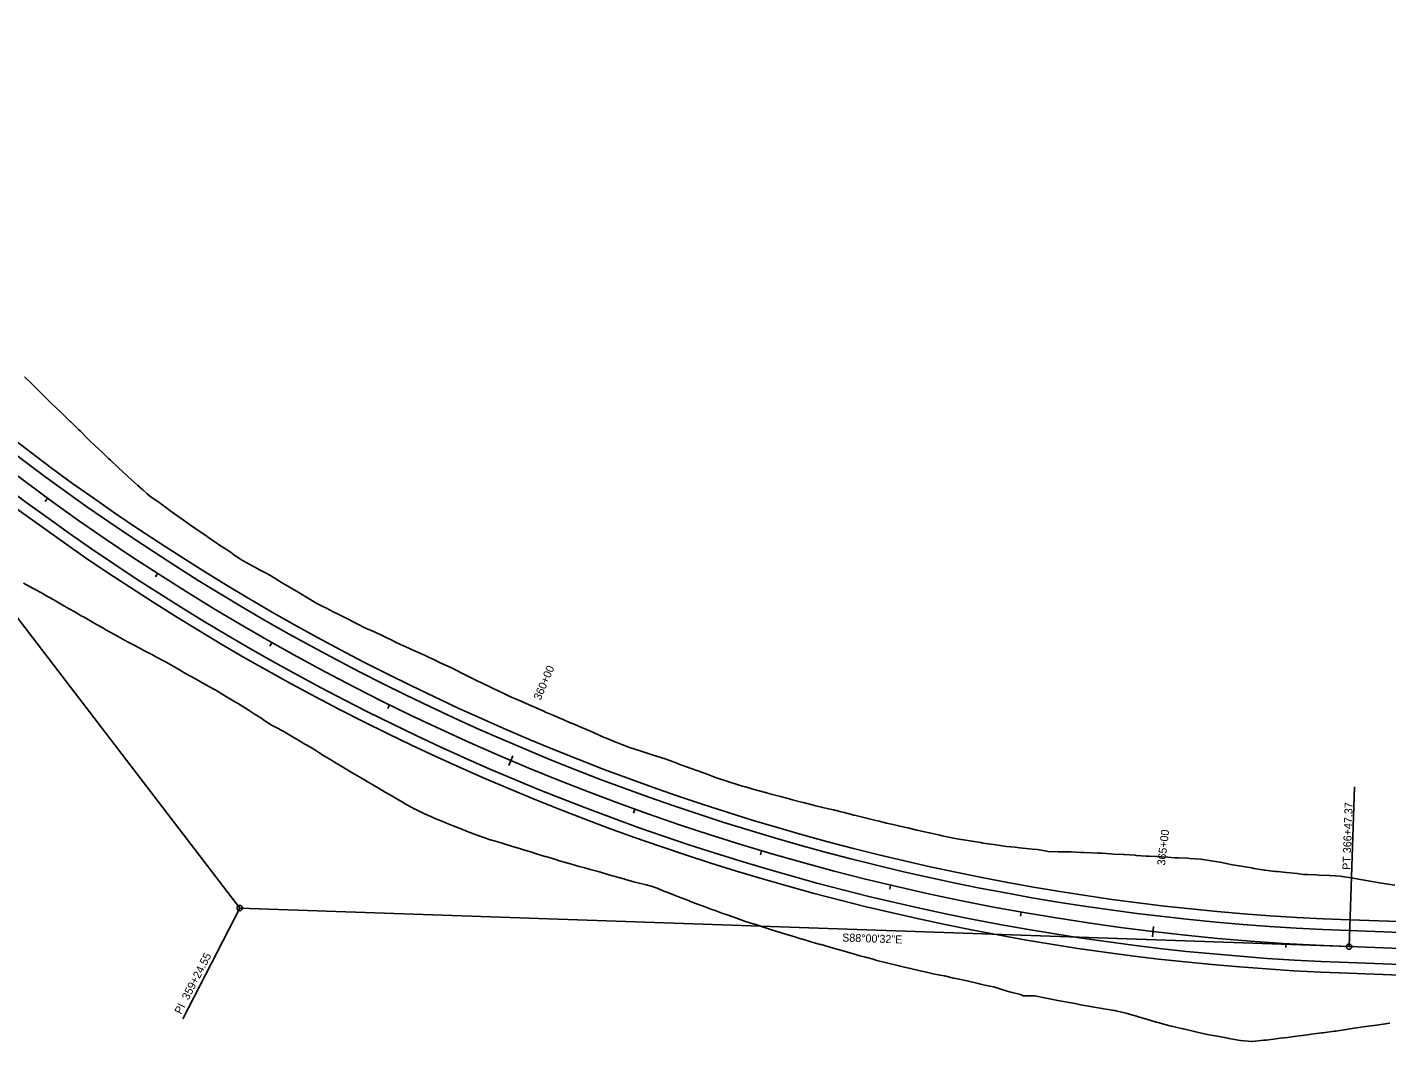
# Model space of a CAD drawing. Extents: x 881426 to 887360, y 1564404 to 1567430.
# Drawn here: x 884680 to 885699, y 1564437 to 1565198 of the extents above; entities that cross this region are included whole.
import ezdxf

# ---------------------------------------------------------------- set-up
doc = ezdxf.new("R2010")
doc.units = 0
for name, color, linetype in [('R_Horz Alg', 7, 'Continuous'), ('R_Horz Alg Annot', 7, 'Continuous'), ('R_Proposed Const Limits_Cut', 7, 'Continuous'), ('R_Proposed Const Limits_Fill', 7, 'Continuous'), ('R_Proposed Road_Lane', 7, 'Continuous'), ('R_Proposed Road_Shoulder', 7, 'Continuous')]:
    doc.layers.add(name, color=color, linetype=linetype)

msp = doc.modelspace()

# ---------------------------------------------------------------- linework, layer by layer
at = {"layer": 'R_Horz Alg'}
msp.add_line((885670.6, 1564508.7), (887357.7, 1564450), dxfattribs=at)
msp.add_arc((885731.8, 1566270.6), 1762.9, 217.4722, 268.0089, dxfattribs=at)
at = {"layer": 'R_Horz Alg Annot'}
for p, q in [((884332.7, 1565198), (884838.9, 1564537.6)), ((884838.9, 1564537.6), (885670.6, 1564508.7))]:
    msp.add_line(p, q, dxfattribs=at)
for points in [[(884693.1, 1564842.4), (884694.8, 1564844.9)], [(884775.7, 1564785.9), (884777.3, 1564788.4)], [(884861.4, 1564734), (884862.9, 1564736.6)], [(884949.9, 1564687.2), (884951.2, 1564689.9)], [(885043.7, 1564651.8), (885040.6, 1564644.5)], [(885670.6, 1564508.7), (885674.7, 1564628.6)], [(885134.2, 1564608.8), (885135.2, 1564611.6)], [(885229.4, 1564577.6), (885230.2, 1564580.5)], [(885326.2, 1564551.9), (885326.8, 1564554.8)], [(884838.9, 1564537.6), (884796.1, 1564454.5)], [(885424.2, 1564531.6), (885424.8, 1564534.6)], [(885524.1, 1564523.9), (885523.2, 1564516)], [(885623.1, 1564508), (885623.3, 1564511)]]:
    msp.add_lwpolyline(points, dxfattribs=at)
for centre in [(884838.9, 1564537.6), (885670.6, 1564508.7)]:
    msp.add_circle(centre, 2, dxfattribs=at)
at = {"layer": 'R_Proposed Const Limits_Cut'}
for points in [[(884841.5, 1564797.9), (884847, 1564794.9), (884850.1, 1564793.3), (884854.2, 1564791), (884858.7, 1564788.6), (884861.4, 1564787.1), (884867.1, 1564783.7), (884868.5, 1564782.8), (884875.4, 1564778.6), (884875.5, 1564778.6), (884882.6, 1564774.5), (884883.9, 1564773.7), (884889.6, 1564770.3), (884892.2, 1564768.6), (884896.6, 1564766)], [(885127.3, 1564659.4), (885131.2, 1564658.1), (885135.1, 1564656.8), (885140.5, 1564655.1), (885142.9, 1564654.3), (885149.7, 1564652.1), (885150.7, 1564651.7), (885158.5, 1564649.3), (885159, 1564649.1), (885166.2, 1564646.4), (885168.2, 1564645.6), (885173.9, 1564643.5), (885177.3, 1564642.2), (885181.6, 1564640.7), (885186.5, 1564638.9), (885189.3, 1564637.9), (885195.7, 1564635.6), (885197, 1564635.1), (885204.8, 1564632.4), (885204.9, 1564632.4)]]:
    msp.add_lwpolyline(points, dxfattribs=at)
at = {"layer": 'R_Proposed Const Limits_Fill'}
for points in [[(884677.6, 1564936), (884683, 1564930.6), (884684.5, 1564929.1), (884688.8, 1564924.8), (884691.4, 1564922.2), (884694.6, 1564919.1), (884698.3, 1564915.4), (884700.5, 1564913.3), (884705.4, 1564908.7), (884706.4, 1564907.7), (884712.3, 1564902), (884712.4, 1564901.9), (884718.2, 1564896.2), (884719.4, 1564895.1), (884724, 1564890.4), (884726.3, 1564888.2), (884729.9, 1564884.7), (884733.4, 1564881.4), (884735.9, 1564879.1), (884740.6, 1564874.8), (884742, 1564873.5), (884747.7, 1564868), (884747.9, 1564867.8), (884753.9, 1564862.1), (884754.9, 1564861.3), (884760.1, 1564856.6), (884762.2, 1564854.8), (884766.3, 1564851.2), (884769.6, 1564848.3), (884772.6, 1564845.8), (884777.4, 1564842.4), (884779.2, 1564841.1), (884785.2, 1564836.6), (884785.8, 1564836.2), (884792.5, 1564831.4), (884793.2, 1564831), (884799.2, 1564826.7), (884801.1, 1564825.3), (884805.9, 1564821.9), (884809.1, 1564819.7), (884812.7, 1564817.4), (884817.2, 1564814.3), (884819.4, 1564812.7), (884825.3, 1564808.7), (884826.2, 1564808.1), (884833.1, 1564803.6), (884833.4, 1564803.3), (884839.8, 1564798.9), (884841.5, 1564797.9)], [(884676.7, 1564781.3), (884684, 1564777.2), (884684.3, 1564777.1), (884692, 1564772.9), (884693.1, 1564772.2), (884699.6, 1564768.6), (884702.1, 1564767.1), (884707.1, 1564764.1), (884711.1, 1564761.9), (884714.7, 1564759.9), (884720.1, 1564756.8), (884722.3, 1564755.6), (884729.1, 1564751.7), (884729.8, 1564751.3), (884737.4, 1564747), (884738.1, 1564746.6), (884745, 1564742.8), (884747.2, 1564741.6), (884752.6, 1564738.6), (884756.3, 1564736.6), (884760.3, 1564734.5), (884765.3, 1564731.7), (884767.9, 1564730.3), (884774.5, 1564726.9), (884775.6, 1564726.3), (884783.3, 1564722.3), (884783.6, 1564722.1), (884790.8, 1564717.9), (884792.5, 1564716.9), (884798.3, 1564713.6), (884801.5, 1564711.8), (884805.8, 1564709.4), (884810.5, 1564706.8), (884813.4, 1564705.1), (884819.5, 1564701.7), (884820.9, 1564700.9), (884828.3, 1564696.5), (884828.3, 1564696.5), (884835.8, 1564692), (884837.1, 1564691.2), (884843.2, 1564687.5), (884845.9, 1564685.8), (884850.5, 1564682.8), (884854.6, 1564680.2), (884857.8, 1564678.1), (884863.3, 1564674.6), (884865.1, 1564673.5), (884872.4, 1564669.8), (884872.8, 1564669.6), (884880.2, 1564665.1), (884881.2, 1564664.5), (884887.7, 1564660.6), (884890.1, 1564659.2), (884895.1, 1564656.2), (884898.9, 1564653.8), (884902.5, 1564651.6), (884907.8, 1564648.4), (884910, 1564647.1), (884916.6, 1564643.1), (884917.4, 1564642.6), (884924.9, 1564638.1), (884925.5, 1564637.7), (884932.4, 1564633.7), (884934.4, 1564632.5), (884939.9, 1564629.2), (884943.4, 1564627.2), (884947.4, 1564624.8), (884952.3, 1564622), (884955, 1564620.4), (884961.3, 1564616.8), (884962.5, 1564616.1), (884970.1, 1564611.8), (884970.4, 1564611.7), (884978, 1564608), (884979.8, 1564607.3), (884986, 1564604.6), (884989.2, 1564603.2), (884994, 1564601.3), (884998.9, 1564599.3), (885002.1, 1564598), (885008.5, 1564595.5), (885010.2, 1564594.9), (885018.2, 1564591.9), (885018.4, 1564591.9), (885026.6, 1564588.9), (885028, 1564588.5), (885035, 1564586.5), (885038, 1564585.6), (885043.3, 1564583.9), (885047.9, 1564582.5), (885051.7, 1564581.4), (885057.8, 1564579.6), (885060, 1564578.9), (885067.7, 1564576.4), (885068.3, 1564576.2), (885076.6, 1564573.7), (885077.6, 1564573.4), (885085, 1564571.3), (885087.6, 1564570.6), (885093.3, 1564568.9), (885097.5, 1564567.8), (885101.7, 1564566.6), (885107.5, 1564565), (885110.1, 1564564.3), (885117.3, 1564562), (885118.4, 1564561.7), (885126.8, 1564559.5), (885127.3, 1564559.3), (885135.1, 1564557.1), (885137.3, 1564556.6), (885143.5, 1564555), (885147.3, 1564554), (885151.8, 1564552.5), (885156.9, 1564550.4), (885159.8, 1564549.2), (885166.5, 1564546.6), (885167.9, 1564546.1), (885176, 1564543), (885176.1, 1564542.9), (885184.1, 1564539.9), (885185.8, 1564539.3), (885192.2, 1564536.9), (885195.4, 1564535.7), (885200.4, 1564533.9), (885205.1, 1564532.2), (885208.5, 1564531), (885214.9, 1564528.7), (885216.7, 1564528.1), (885224.7, 1564525.6), (885225, 1564525.5), (885233.2, 1564522.7), (885234.5, 1564522.3), (885241.5, 1564520.1), (885244.3, 1564519.3), (885249.7, 1564517.5), (885254.2, 1564516.2), (885258, 1564515), (885264.1, 1564513.3), (885266.4, 1564512.6), (885274, 1564510.4), (885274.7, 1564510.2), (885283, 1564507.8), (885283.9, 1564507.6), (885291.4, 1564505.5), (885293.8, 1564504.8), (885299.7, 1564503.1), (885303.8, 1564501.9), (885308.1, 1564500.7), (885313.7, 1564499.2), (885316.5, 1564498.4), (885323.7, 1564496.6), (885324.9, 1564496.3), (885333.3, 1564494.2), (885333.7, 1564494.1), (885341.8, 1564492.4), (885343.8, 1564491.9), (885350.2, 1564490.4), (885353.9, 1564489.5), (885358.7, 1564488.4), (885364, 1564487.3), (885367.2, 1564486.7), (885374.1, 1564485.1), (885375.7, 1564484.7), (885384.2, 1564483), (885384.2, 1564483), (885392.6, 1564481), (885394.2, 1564480.6), (885401.1, 1564479.2), (885404.3, 1564478.5), (885409.5, 1564476.8), (885414.3, 1564475.4), (885417.9, 1564474.4), (885424.3, 1564472.8), (885426.3, 1564471.8), (885434.7, 1564471.8), (885435.1, 1564471.8), (885443.6, 1564470.1), (885444.8, 1564469.9), (885452.2, 1564468.4), (885455, 1564467.9), (885460.7, 1564466.8), (885465.2, 1564466), (885469.3, 1564465.2), (885475.4, 1564464.1), (885477.9, 1564463.7), (885485.6, 1564462.4), (885486.4, 1564462.2), (885495, 1564460.8), (885495.8, 1564460.6), (885503.6, 1564458.9), (885505.9, 1564458.1), (885512, 1564456.3), (885516, 1564455.1), (885520.5, 1564453.8), (885526.1, 1564452.2), (885528.5, 1564451.5), (885529, 1564451.4), (885536.2, 1564449.4), (885537.5, 1564449.1), (885546.1, 1564447.1), (885546.4, 1564447), (885554.7, 1564445), (885556.6, 1564444.6), (885563.3, 1564443), (885566.9, 1564442.4), (885572, 1564441.7), (885577.2, 1564440.5), (885580.6, 1564439.8), (885587.5, 1564438.6), (885589.3, 1564438.4), (885597.8, 1564437.5), (885598, 1564437.5), (885606.8, 1564438.5), (885608.4, 1564438.7), (885615.7, 1564439.6), (885618.9, 1564440), (885624.5, 1564440.7), (885629.4, 1564441.3), (885633.3, 1564441.9), (885639.8, 1564442.7), (885642.1, 1564443), (885650.3, 1564444), (885650.9, 1564444.1), (885659.7, 1564445.3), (885660.7, 1564445.4), (885668.4, 1564446.6), (885671.1, 1564447), (885681.1, 1564448.6), (885691.2, 1564449.8), (885701.2, 1564451.3)], [(884896.6, 1564766), (884900.8, 1564763.9), (884904, 1564762.4), (884909.5, 1564759.5), (884911.3, 1564758.6), (884918.2, 1564755.2), (884918.6, 1564755), (884926, 1564751.3), (884927, 1564750.8), (884933.3, 1564747.6), (884935.7, 1564746.5), (884940.8, 1564744.2), (884944.6, 1564742.5), (884948.2, 1564740.8), (884953.4, 1564738.2), (884955.6, 1564737.1), (884962.2, 1564734), (884963, 1564733.7), (884970.4, 1564730.3), (884971.1, 1564730), (884977.9, 1564726.9), (884980, 1564726), (884985.4, 1564723.5), (884988.7, 1564721.8), (884992.7, 1564719.9), (884997.6, 1564717.7), (885000.1, 1564716.4), (885006.3, 1564713.3), (885007.5, 1564712.7), (885014.8, 1564709.1), (885015, 1564709), (885022.2, 1564705.5), (885023.8, 1564704.7), (885029.5, 1564701.9), (885032.6, 1564700.5), (885036.9, 1564698.4), (885041.4, 1564696.3), (885044.4, 1564695), (885050.4, 1564692.5), (885051.9, 1564691.8), (885059.3, 1564688.5), (885059.4, 1564688.4), (885067, 1564685.2), (885068.2, 1564684.6), (885074.4, 1564681.9), (885077.2, 1564680.7), (885082, 1564678.7), (885086.1, 1564676.8), (885089.5, 1564675.4), (885095.1, 1564673.1), (885097.1, 1564672.2), (885104.1, 1564669.2), (885104.6, 1564668.9), (885112.1, 1564665.6), (885113, 1564665.2), (885119.7, 1564662.4), (885122, 1564661.4), (885127.3, 1564659.4)], [(885204.9, 1564632.4), (885212.6, 1564629.9), (885214.2, 1564629.5), (885220.5, 1564627.7), (885223.6, 1564626.8), (885228.4, 1564625.5), (885233, 1564624.2), (885236.3, 1564623.3), (885242.4, 1564621.7), (885244.2, 1564621.2), (885251.9, 1564619.2), (885252.2, 1564619.1), (885260.1, 1564617), (885261.3, 1564616.7), (885268.1, 1564615), (885270.8, 1564614.4), (885276, 1564613), (885280.3, 1564612), (885284, 1564611.2), (885289.8, 1564609.8), (885292, 1564609.3), (885299.2, 1564607.4), (885299.9, 1564607.2), (885307.9, 1564605.3), (885308.7, 1564605.1), (885315.8, 1564603.4), (885318.2, 1564602.8), (885323.8, 1564601.4), (885327.6, 1564600.5), (885331.8, 1564599.6), (885337.1, 1564598.4), (885339.7, 1564597.8), (885346.6, 1564596.1), (885347.7, 1564595.9), (885355.7, 1564594.1), (885356.1, 1564594.1), (885363.7, 1564592.3), (885365.6, 1564591.9), (885371.7, 1564590.5), (885375.2, 1564589.8), (885379.8, 1564589), (885384.8, 1564588.2), (885387.8, 1564587.7), (885394.4, 1564586.7), (885395.9, 1564586.4), (885404.1, 1564585.2), (885404.1, 1564585.2), (885412.2, 1564584.1), (885413.7, 1564583.9), (885420.3, 1564583.2), (885423.4, 1564582.8), (885428.5, 1564582.2), (885433.1, 1564581.9), (885436.7, 1564581.6), (885442.8, 1564580.5), (885444.7, 1564580.1), (885452.5, 1564579.8), (885452.9, 1564579.8), (885461.2, 1564579.7), (885462.3, 1564579.7), (885469.4, 1564579.4), (885472.1, 1564579.2), (885477.6, 1564579), (885481.9, 1564578.9), (885485.8, 1564578.7), (885491.5, 1564578.2), (885493.9, 1564578), (885501.3, 1564577.8), (885502.1, 1564577.7), (885510.3, 1564577.2), (885511, 1564577.1), (885518.4, 1564576.6), (885520.7, 1564576.6), (885526.6, 1564576.3), (885530.3, 1564576), (885534.7, 1564575.7), (885540, 1564575.4), (885542.3, 1564575.4), (885542.8, 1564575.4), (885549.7, 1564575), (885551, 1564574.9), (885559.1, 1564574.4), (885559.4, 1564574.4), (885567.1, 1564573.1), (885568.9, 1564572.8), (885575.2, 1564571.7), (885578.5, 1564571), (885583.2, 1564570.1), (885588.1, 1564569.3), (885591.2, 1564568.8), (885597.6, 1564567.7), (885599.3, 1564567.4), (885607.2, 1564566), (885607.4, 1564566), (885615.5, 1564565.1), (885616.9, 1564565), (885623.6, 1564564.4), (885626.5, 1564564.1), (885631.7, 1564563.5), (885636.2, 1564562.9), (885639.8, 1564562.8), (885645.9, 1564562.5), (885648, 1564562.4), (885655.6, 1564562), (885656.1, 1564562), (885664.3, 1564561.5), (885665.2, 1564561.4), (885672.4, 1564560.2), (885675, 1564559.7), (885684.9, 1564558.1), (885694.9, 1564556.4), (885704.8, 1564554.8)]]:
    msp.add_lwpolyline(points, dxfattribs=at)
at = {"layer": 'R_Proposed Road_Lane'}
for p, q in [((885671, 1564520.7), (887147.7, 1564469.3)), ((885670.2, 1564496.7), (887146.9, 1564445.4))]:
    msp.add_line(p, q, dxfattribs=at)
for radius in [1750.9, 1774.9]:
    msp.add_arc((885731.8, 1566270.6), radius, 226.4099, 268.0089, dxfattribs=at)
at = {"layer": 'R_Proposed Road_Shoulder'}
for p, q in [((885671.3, 1564528.7), (887148, 1564477.3)), ((885669.9, 1564488.7), (887146.6, 1564437.4))]:
    msp.add_line(p, q, dxfattribs=at)
for radius in [1742.9, 1782.9]:
    msp.add_arc((885731.8, 1566270.6), radius, 226.4099, 268.0089, dxfattribs=at)

# ---------------------------------------------------------------- texts
at = {"layer": 'R_Horz Alg Annot'}
for s, rotation, p in [('360+00', 66.9693, (885064.4, 1564693)), ('PT 366+47.37', 88.0089, (885671.6, 1564566.2)), ('365+00', 83.2193, (885532.6, 1564569.3)), ('S88%%d00\'32"E', 358.0089, (885290.5, 1564512.6)), ('PI  359+24.55', 62.7406, (884794.9, 1564457.5))]:
    msp.add_text(s, height=6, rotation=rotation, dxfattribs=at).set_placement(p)

doc.saveas('drawing.dxf')
